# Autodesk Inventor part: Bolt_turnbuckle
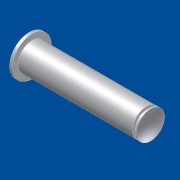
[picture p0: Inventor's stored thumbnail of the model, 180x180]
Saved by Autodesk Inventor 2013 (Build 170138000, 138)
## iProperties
Shininess: 69.0
Length Units: 11269
Angle Units: 11279
Time Units: 11290
Mass Units: 11283
Length Display Precision: 3
Angle Display Precision: 2
Created: 2001-04
Part Number: Bolt_turnbuckle
Material: Standard
Document SubType Name: Modellieren
Designer: dl
Density: 1 g/cm^3
Density: 0.0
Volumn: 0.0
Area: 0.0
PropertySet Name: Model Information
Control State: 0
Master: False
Checked Out: False
Author: dl
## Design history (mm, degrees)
body "Solid1"
revolve "Revolution1" stored, may be unused: angle "d8" = 90 deg
sketch "Sketch1"
  geometry: L1 (-47.127, 11.057)-(-46.627, 11.057); L2 (-46.627, 11.057)-(-46.627, 10.057); L3 (-46.627, 10.057)-(-26.127, 10.057); L4 (-26.127, 10.057)-(-26.127, 9.557); L5 (-26.127, 9.557)-(-25.627, 9.557); L6 (-25.627, 9.557)-(-25.627, 10.057); L7 (-25.627, 10.057)-(-25.377, 10.057); L8 (-47.598, 7.557)-(-24.85, 7.557); A1 r 13.226 centre (-34.372, 7.557) between (-47.127, 11.057) and (-47.598, 7.557); A2 r 6.195 centre (-31.044, 7.557) between (-24.85, 7.557) and (-25.377, 10.057)
  constraints: 16 end point, 7 parallel, 4 point on circle, 2 centre point, 1 collinear, 1 horizontal, 1 perpendicular
  dimensions: "d0" = 2.5 distance between parallel lines of L8 L3; "d1" = 0 distance from line of L8 A2.centre; "d2" = 0 distance from line of L8 A1.centre; "d3" = 0.5 distance of L1.start L1.end; "d4" = 3.5 vertical distance of L8.start L1.start; "d5" = 0.5 distance of L4.end L5.end; "d6" = 0.25 distance of L6.end L7.end; "d7" = 0.5 distance of L5.end L6.end; "d9" = 20.5 distance from line of L4.end L2
